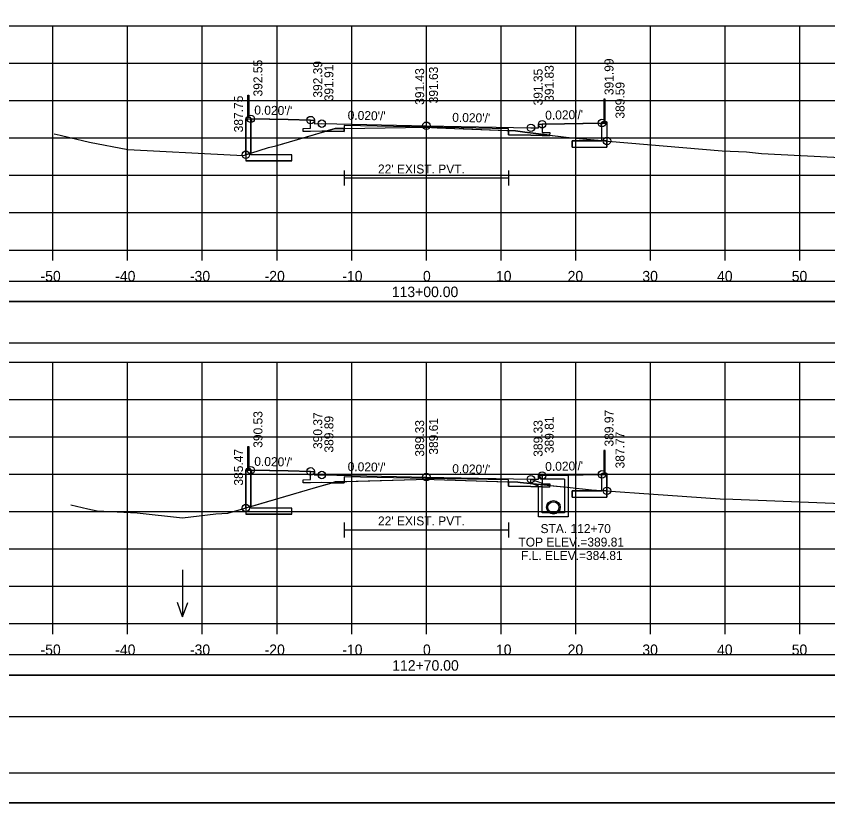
# Model space of a CAD drawing. Extents: x -37291014 to -37290680, y -936053 to -933067.
# Drawn here: x -37290898 to -37290789.4, y -933493.3 to -933388 of the extents above; entities that cross this region are included whole.
import ezdxf

# ---------------------------------------------------------------- set-up
doc = ezdxf.new("R2010")
doc.units = 0
for name, color, linetype in [('Default', 7, 'Continuous'), ('R_Alt Surface', 7, 'Continuous'), ('R_Axis', 7, 'Continuous'), ('R_Axis Annot', 7, 'Continuous'), ('R_Border', 7, 'Continuous'), ('R_Contours', 7, 'Continuous'), ('R_Exist Surface', 7, 'Continuous'), ('R_Fin Surface', 7, 'Continuous'), ('R_Grid', 7, 'Continuous'), ('R_No Plot', 7, 'Continuous'), ('R_Water', 7, 'Continuous'), ('R_Water Annot', 7, 'Continuous'), ('R_Xsect Elev', 7, 'Continuous'), ('R_Xsect Slope', 7, 'Continuous')]:
    doc.layers.add(name, color=color, linetype=linetype)

msp = doc.modelspace()

# ---------------------------------------------------------------- linework, layer by layer
at = {"layer": 'Default'}
for p, q in [((-37290867.02, -933401.53), (-37290867.02, -933398.53)), ((-37290867.02, -933398.53), (-37290866.85, -933398.53)), ((-37290866.85, -933398.53), (-37290866.85, -933401.53)), ((-37290819.35, -933399.09), (-37290819.35, -933402.09)), ((-37290819.18, -933399.09), (-37290819.35, -933399.09)), ((-37290819.18, -933402.09), (-37290819.18, -933399.09)), ((-37290867.21, -933401.55), (-37290867.27, -933401.61)), ((-37290867.27, -933401.61), (-37290867.27, -933407.35)), ((-37290866.66, -933401.53), (-37290867.21, -933401.53)), ((-37290867.21, -933401.53), (-37290867.21, -933401.55)), ((-37290866.66, -933401.55), (-37290867.21, -933401.55)), ((-37290866.66, -933401.55), (-37290866.66, -933401.53)), ((-37290866.6, -933401.61), (-37290866.66, -933401.55)), ((-37290866.6, -933406.52), (-37290866.6, -933401.61)), ((-37290819.6, -933402.17), (-37290819.54, -933402.11)), ((-37290819.6, -933404.68), (-37290819.6, -933402.17)), ((-37290819.54, -933402.09), (-37290819, -933402.09)), ((-37290819.54, -933402.11), (-37290819.54, -933402.09)), ((-37290819.54, -933402.11), (-37290819, -933402.11)), ((-37290819, -933402.09), (-37290819, -933402.11)), ((-37290819, -933402.11), (-37290818.93, -933402.17)), ((-37290818.93, -933402.17), (-37290818.93, -933405.51)), ((-37290823.6, -933405.51), (-37290823.6, -933404.68)), ((-37290823.6, -933404.68), (-37290819.6, -933404.68)), ((-37290823.6, -933405.51), (-37290818.93, -933405.51)), ((-37290861.1, -933406.52), (-37290866.6, -933406.52)), ((-37290861.1, -933407.35), (-37290861.1, -933406.52)), ((-37290861.1, -933407.35), (-37290867.27, -933407.35)), ((-37290867.02, -933448.56), (-37290867.02, -933445.56)), ((-37290867.02, -933445.56), (-37290866.85, -933445.56)), ((-37290866.85, -933445.56), (-37290866.85, -933448.56)), ((-37290819.35, -933446.12), (-37290819.35, -933449.12)), ((-37290819.18, -933446.12), (-37290819.35, -933446.12)), ((-37290819.18, -933449.12), (-37290819.18, -933446.12)), ((-37290867.21, -933448.58), (-37290867.27, -933448.64)), ((-37290867.27, -933448.64), (-37290867.27, -933454.63)), ((-37290866.66, -933448.56), (-37290867.21, -933448.56)), ((-37290867.21, -933448.56), (-37290867.21, -933448.58)), ((-37290866.66, -933448.58), (-37290867.21, -933448.58)), ((-37290866.66, -933448.58), (-37290866.66, -933448.56)), ((-37290866.6, -933448.64), (-37290866.66, -933448.58)), ((-37290866.6, -933453.8), (-37290866.6, -933448.64)), ((-37290819.6, -933449.2), (-37290819.54, -933449.14)), ((-37290819.6, -933451.5), (-37290819.6, -933449.2)), ((-37290819.54, -933449.12), (-37290819, -933449.12)), ((-37290819.54, -933449.14), (-37290819.54, -933449.12)), ((-37290819.54, -933449.14), (-37290819, -933449.14)), ((-37290819, -933449.12), (-37290819, -933449.14)), ((-37290819, -933449.14), (-37290818.93, -933449.2)), ((-37290818.93, -933449.2), (-37290818.93, -933452.33)), ((-37290823.6, -933452.33), (-37290823.6, -933451.5)), ((-37290823.6, -933451.5), (-37290819.6, -933451.5)), ((-37290823.6, -933452.33), (-37290818.93, -933452.33)), ((-37290861.1, -933454.63), (-37290867.27, -933454.63)), ((-37290861.1, -933453.8), (-37290866.6, -933453.8)), ((-37290861.1, -933454.63), (-37290861.1, -933453.8))]:
    msp.add_line(p, q, dxfattribs=at)
for points in [[(-37290866.52, -933402.22), (-37290866.6, -933402.22), (-37290866.6, -933401.72), (-37290866.52, -933401.72), (-37290866.52, -933402.22)], [(-37290819.68, -933402.78), (-37290819.6, -933402.78), (-37290819.6, -933402.28), (-37290819.68, -933402.28), (-37290819.68, -933402.78)], [(-37290866.52, -933449.24), (-37290866.6, -933449.24), (-37290866.6, -933448.74), (-37290866.52, -933448.74), (-37290866.52, -933449.24)], [(-37290819.68, -933449.8), (-37290819.6, -933449.8), (-37290819.6, -933449.3), (-37290819.68, -933449.3), (-37290819.68, -933449.8)]]:
    msp.add_lwpolyline(points, dxfattribs=at)
for points in [[(-37290992.31, -933426.17), (-37290693.89, -933426.17), (-37290693.89, -933423.47), (-37290992.31, -933423.47)], [(-37290992.31, -933431.7), (-37290693.89, -933431.7), (-37290693.89, -933426.17), (-37290992.31, -933426.17)], [(-37290992.31, -933476.17), (-37290693.89, -933476.17), (-37290693.89, -933473.47), (-37290992.31, -933473.47)], [(-37290992.31, -933481.7), (-37290693.89, -933481.7), (-37290693.89, -933476.17), (-37290992.31, -933476.17)]]:
    msp.add_lwpolyline(points, close=True, dxfattribs=at)
at = {"layer": 'R_Alt Surface'}
for points in [[(-37290827.6, -933402.44), (-37290827.6, -933403.53), (-37290826.59, -933403.55), (-37290826.6, -933403.97), (-37290827.6, -933403.95), (-37290829.1, -933403.92), (-37290832.1, -933403.86), (-37290832.1, -933403.03), (-37290843.1, -933402.81), (-37290854.1, -933402.59), (-37290854.1, -933403.42), (-37290857.1, -933403.36), (-37290858.6, -933403.39), (-37290859.6, -933403.41), (-37290859.61, -933402.99), (-37290858.6, -933402.97), (-37290858.6, -933401.88)], [(-37290854.1, -933408.63), (-37290854.1, -933410.63)], [(-37290832.1, -933408.63), (-37290832.1, -933410.63)], [(-37290854.1, -933409.63), (-37290832.1, -933409.63)], [(-37290827.6, -933449.46), (-37290827.6, -933450.56), (-37290826.59, -933450.58), (-37290826.6, -933450.99), (-37290827.6, -933450.97), (-37290829.1, -933450.94), (-37290832.1, -933450.88), (-37290832.1, -933450.05), (-37290843.1, -933449.83), (-37290854.1, -933449.61), (-37290854.1, -933450.44), (-37290857.1, -933450.38), (-37290858.6, -933450.41), (-37290859.6, -933450.43), (-37290859.61, -933450.02), (-37290858.6, -933450), (-37290858.6, -933448.9)], [(-37290854.1, -933455.73), (-37290854.1, -933457.73)], [(-37290832.1, -933455.73), (-37290832.1, -933457.73)], [(-37290854.1, -933456.73), (-37290832.1, -933456.73)]]:
    msp.add_lwpolyline(points, dxfattribs=at)
at = {"layer": 'R_Axis'}
for p, q in [((-37290993.1, -933419.27), (-37290693.1, -933419.27)), ((-37290893.1, -933420.67), (-37290893.1, -933419.27)), ((-37290883.1, -933420.67), (-37290883.1, -933419.27)), ((-37290873.1, -933420.67), (-37290873.1, -933419.27)), ((-37290863.1, -933420.67), (-37290863.1, -933419.27)), ((-37290853.1, -933420.67), (-37290853.1, -933419.27)), ((-37290843.1, -933420.67), (-37290843.1, -933419.27)), ((-37290833.1, -933420.67), (-37290833.1, -933419.27)), ((-37290823.1, -933420.67), (-37290823.1, -933419.27)), ((-37290813.1, -933420.67), (-37290813.1, -933419.27)), ((-37290803.1, -933420.67), (-37290803.1, -933419.27)), ((-37290793.1, -933420.67), (-37290793.1, -933419.27)), ((-37290993.1, -933469.27), (-37290693.1, -933469.27)), ((-37290893.1, -933470.67), (-37290893.1, -933469.27)), ((-37290883.1, -933470.67), (-37290883.1, -933469.27)), ((-37290873.1, -933470.67), (-37290873.1, -933469.27)), ((-37290863.1, -933470.67), (-37290863.1, -933469.27)), ((-37290853.1, -933470.67), (-37290853.1, -933469.27)), ((-37290843.1, -933470.67), (-37290843.1, -933469.27)), ((-37290833.1, -933470.67), (-37290833.1, -933469.27)), ((-37290823.1, -933470.67), (-37290823.1, -933469.27)), ((-37290813.1, -933470.67), (-37290813.1, -933469.27)), ((-37290803.1, -933470.67), (-37290803.1, -933469.27)), ((-37290793.1, -933470.67), (-37290793.1, -933469.27))]:
    msp.add_line(p, q, dxfattribs=at)
at = {"layer": 'R_Border'}
msp.add_line((-37290684.92, -933489.27), (-37291001.1, -933489.27), dxfattribs=at)
at = {"layer": 'R_Contours'}
for p, q in [((-37290866.6, -933402.22), (-37290866.6, -933406.3)), ((-37290856.56, -933403.37), (-37290854.1, -933403.42)), ((-37290854.1, -933403.42), (-37290854.1, -933402.99)), ((-37290832.1, -933403.29), (-37290832.1, -933403.03)), ((-37290832.1, -933403.29), (-37290832.1, -933403.86)), ((-37290819.6, -933404.62), (-37290819.6, -933402.78)), ((-37290819.6, -933404.68), (-37290823.6, -933404.68)), ((-37290823.6, -933404.68), (-37290823.6, -933405.51)), ((-37290818.93, -933404.68), (-37290819.6, -933404.62)), ((-37290819.6, -933404.62), (-37290819.6, -933404.68)), ((-37290823.6, -933405.51), (-37290818.93, -933405.51)), ((-37290866.6, -933406.3), (-37290867.27, -933406.52)), ((-37290866.6, -933406.52), (-37290866.6, -933406.3)), ((-37290861.1, -933406.52), (-37290866.6, -933406.52)), ((-37290861.1, -933407.35), (-37290861.1, -933406.52)), ((-37290867.27, -933407.35), (-37290861.1, -933407.35)), ((-37290866.6, -933449.24), (-37290866.6, -933453.61)), ((-37290855.71, -933450.41), (-37290854.1, -933450.44)), ((-37290854.1, -933450.44), (-37290854.1, -933450.25)), ((-37290832.1, -933450.3), (-37290832.1, -933450.05)), ((-37290832.1, -933450.3), (-37290832.1, -933450.88)), ((-37290826.6, -933450.79), (-37290824.25, -933451.03)), ((-37290819.6, -933451.5), (-37290823.6, -933451.5)), ((-37290823.6, -933451.5), (-37290823.6, -933452.33)), ((-37290819.6, -933451.45), (-37290819.6, -933451.5)), ((-37290818.93, -933451.5), (-37290819.6, -933451.45)), ((-37290823.6, -933452.33), (-37290818.93, -933452.33)), ((-37290866.6, -933453.61), (-37290867.27, -933453.8)), ((-37290866.6, -933453.8), (-37290866.6, -933453.61)), ((-37290867.27, -933454.63), (-37290861.1, -933454.63)), ((-37290861.1, -933453.8), (-37290866.6, -933453.8)), ((-37290861.1, -933454.63), (-37290861.1, -933453.8))]:
    msp.add_line(p, q, dxfattribs=at)
for points in [[(-37290866.52, -933401.72), (-37290866.52, -933402.22), (-37290866.6, -933402.22)], [(-37290858.6, -933401.88), (-37290861.6, -933401.82), (-37290866.52, -933401.72)], [(-37290856.56, -933403.37), (-37290857.1, -933403.36), (-37290858.6, -933403.39), (-37290859.6, -933403.41), (-37290859.61, -933402.99), (-37290858.6, -933402.97), (-37290858.6, -933401.88)], [(-37290832.1, -933403.03), (-37290843.1, -933402.81), (-37290854.1, -933402.59), (-37290854.1, -933402.99)], [(-37290819.68, -933402.28), (-37290824.6, -933402.38), (-37290827.6, -933402.44)], [(-37290827.6, -933402.44), (-37290827.6, -933403.53), (-37290826.59, -933403.55), (-37290826.6, -933403.9)], [(-37290819.6, -933402.78), (-37290819.68, -933402.78), (-37290819.68, -933402.28)], [(-37290866.6, -933406.3), (-37290864.22, -933405.53), (-37290863.27, -933405.31), (-37290856.56, -933403.37)], [(-37290854.1, -933402.99), (-37290855.3, -933403), (-37290856.56, -933403.37)], [(-37290854.1, -933402.99), (-37290854.05, -933402.99), (-37290843.19, -933402.84), (-37290841.66, -933402.9), (-37290832.1, -933403.29)], [(-37290826.6, -933403.9), (-37290829.94, -933403.48), (-37290831.18, -933403.33), (-37290832.1, -933403.29)], [(-37290832.1, -933403.86), (-37290829.1, -933403.92), (-37290827.6, -933403.95), (-37290826.6, -933403.97), (-37290826.6, -933403.9)], [(-37290826.6, -933403.9), (-37290823.64, -933404.27), (-37290819.6, -933404.62)], [(-37290818.93, -933405.51), (-37290818.93, -933404.68), (-37290818.93, -933404.68)], [(-37290867.27, -933406.52), (-37290867.27, -933406.52), (-37290867.27, -933407.35)], [(-37290866.52, -933448.74), (-37290866.52, -933449.24), (-37290866.6, -933449.24)], [(-37290858.6, -933448.9), (-37290861.6, -933448.84), (-37290866.52, -933448.74)], [(-37290855.71, -933450.41), (-37290857.1, -933450.38), (-37290858.6, -933450.41), (-37290859.6, -933450.43), (-37290859.61, -933450.02), (-37290858.6, -933450), (-37290858.6, -933448.9)], [(-37290818.93, -933451.5), (-37290818.93, -933449.3), (-37290819.6, -933449.3), (-37290824.6, -933449.4), (-37290827.6, -933449.46)], [(-37290866.6, -933453.61), (-37290858.25, -933451.16), (-37290855.71, -933450.41)], [(-37290854.1, -933450.25), (-37290855.3, -933450.29), (-37290855.71, -933450.41)], [(-37290832.1, -933450.05), (-37290843.1, -933449.83), (-37290854.1, -933449.61), (-37290854.1, -933450.25)], [(-37290854.1, -933450.25), (-37290844.46, -933449.97), (-37290843.27, -933449.93), (-37290842.07, -933449.97), (-37290832.1, -933450.3)], [(-37290826.6, -933450.79), (-37290830.56, -933450.39), (-37290830.84, -933450.34), (-37290832.1, -933450.3)], [(-37290827.6, -933449.46), (-37290827.6, -933450.56), (-37290826.59, -933450.58), (-37290826.6, -933450.79)], [(-37290832.1, -933450.88), (-37290829.1, -933450.94), (-37290827.6, -933450.97), (-37290826.6, -933450.99), (-37290826.6, -933450.79)], [(-37290824.25, -933451.03), (-37290820.98, -933451.35), (-37290818.93, -933451.5)], [(-37290818.93, -933452.33), (-37290818.93, -933451.5), (-37290818.93, -933451.5)], [(-37290867.27, -933453.8), (-37290867.27, -933453.8), (-37290867.27, -933454.63)]]:
    msp.add_lwpolyline(points, dxfattribs=at)
at = {"layer": 'R_Exist Surface'}
for points in [[(-37290892.92, -933403.72), (-37290892.15, -933403.91), (-37290890.85, -933404.21), (-37290888.19, -933404.84), (-37290883.08, -933405.8), (-37290869.37, -933406.53), (-37290867.6, -933406.62), (-37290864.22, -933405.53), (-37290863.27, -933405.31), (-37290855.3, -933403), (-37290854.05, -933402.99), (-37290843.19, -933402.84), (-37290841.66, -933402.9), (-37290831.18, -933403.33), (-37290829.94, -933403.48), (-37290823.64, -933404.27), (-37290818.76, -933404.69), (-37290803.51, -933406), (-37290800.23, -933406.12), (-37290798.22, -933406.34), (-37290786.8, -933406.94)], [(-37290890.71, -933453.36), (-37290888.42, -933453.9), (-37290887.18, -933454.2), (-37290881.8, -933454.45), (-37290875.74, -933455.12), (-37290871.29, -933454.6), (-37290869.68, -933454.51), (-37290858.25, -933451.16), (-37290855.3, -933450.29), (-37290844.46, -933449.97), (-37290843.27, -933449.93), (-37290842.07, -933449.97), (-37290830.84, -933450.34), (-37290830.56, -933450.39), (-37290824.25, -933451.03), (-37290820.98, -933451.35), (-37290810.78, -933452.07), (-37290803.79, -933452.58), (-37290802.09, -933452.63), (-37290784.1, -933453.35)]]:
    msp.add_lwpolyline(points, dxfattribs=at)
at = {"layer": 'R_Fin Surface'}
for points in [[(-37290867.27, -933406.52), (-37290867.27, -933401.72), (-37290866.6, -933401.72), (-37290861.6, -933401.82), (-37290858.6, -933401.88), (-37290858.1, -933401.88), (-37290858.1, -933402.38), (-37290857.1, -933402.36), (-37290843.1, -933402.64), (-37290829.1, -933402.92), (-37290828.1, -933402.94), (-37290828.1, -933402.44), (-37290827.6, -933402.44), (-37290824.6, -933402.38), (-37290819.6, -933402.28), (-37290818.93, -933402.28), (-37290818.93, -933404.68)], [(-37290867.27, -933453.8), (-37290867.27, -933448.74), (-37290866.6, -933448.74), (-37290861.6, -933448.84), (-37290858.6, -933448.9), (-37290858.1, -933448.9), (-37290858.1, -933449.4), (-37290857.1, -933449.38), (-37290843.1, -933449.66), (-37290829.1, -933449.94), (-37290828.1, -933449.96), (-37290828.1, -933449.46), (-37290827.6, -933449.46), (-37290824.6, -933449.4), (-37290819.6, -933449.3), (-37290818.93, -933449.3), (-37290818.93, -933451.5)]]:
    msp.add_lwpolyline(points, dxfattribs=at)
at = {"layer": 'R_Grid'}
for p, q in [((-37290993.1, -933389.27), (-37290693.1, -933389.27)), ((-37290893.1, -933419.27), (-37290893.1, -933389.27)), ((-37290883.1, -933419.27), (-37290883.1, -933389.27)), ((-37290873.1, -933419.27), (-37290873.1, -933389.27)), ((-37290863.1, -933419.27), (-37290863.1, -933389.27)), ((-37290853.1, -933419.27), (-37290853.1, -933389.27)), ((-37290843.1, -933419.27), (-37290843.1, -933389.27)), ((-37290833.1, -933419.27), (-37290833.1, -933389.27)), ((-37290823.1, -933419.27), (-37290823.1, -933389.27)), ((-37290813.1, -933419.27), (-37290813.1, -933389.27)), ((-37290803.1, -933419.27), (-37290803.1, -933389.27)), ((-37290793.1, -933419.27), (-37290793.1, -933389.27)), ((-37290993.1, -933394.27), (-37290693.1, -933394.27)), ((-37290993.1, -933399.27), (-37290693.1, -933399.27)), ((-37290993.1, -933404.27), (-37290693.1, -933404.27)), ((-37290993.1, -933409.27), (-37290693.1, -933409.27)), ((-37290993.1, -933414.27), (-37290693.1, -933414.27)), ((-37290993.1, -933419.27), (-37290693.1, -933419.27)), ((-37290993.1, -933434.27), (-37290693.1, -933434.27)), ((-37290893.1, -933469.27), (-37290893.1, -933434.27)), ((-37290883.1, -933469.27), (-37290883.1, -933434.27)), ((-37290873.1, -933469.27), (-37290873.1, -933434.27)), ((-37290863.1, -933469.27), (-37290863.1, -933434.27)), ((-37290853.1, -933469.27), (-37290853.1, -933434.27)), ((-37290843.1, -933469.27), (-37290843.1, -933434.27)), ((-37290833.1, -933469.27), (-37290833.1, -933434.27)), ((-37290823.1, -933469.27), (-37290823.1, -933434.27)), ((-37290813.1, -933469.27), (-37290813.1, -933434.27)), ((-37290803.1, -933469.27), (-37290803.1, -933434.27)), ((-37290793.1, -933469.27), (-37290793.1, -933434.27)), ((-37290993.1, -933439.27), (-37290693.1, -933439.27)), ((-37290993.1, -933444.27), (-37290693.1, -933444.27)), ((-37290993.1, -933449.27), (-37290693.1, -933449.27)), ((-37290993.1, -933454.27), (-37290693.1, -933454.27)), ((-37290993.1, -933459.27), (-37290693.1, -933459.27)), ((-37290993.1, -933464.27), (-37290693.1, -933464.27)), ((-37290993.1, -933469.27), (-37290693.1, -933469.27))]:
    msp.add_line(p, q, dxfattribs=at)
at = {"layer": 'R_No Plot'}
msp.add_line((-37291013.5, -933493.25), (-37290680.17, -933493.25), dxfattribs=at)
for points in [[(-37291013.51, -933279.91), (-37290680.17, -933279.91), (-37290680.17, -933493.25), (-37291013.51, -933493.25)], [(-37290767.18, -933283.81), (-37290747.56, -933283.81), (-37290747.56, -933293.69), (-37290731.45, -933293.69), (-37290708.25, -933293.69), (-37290708.25, -933318.02), (-37290684.92, -933318.02), (-37290684.92, -933489.27), (-37291001.1, -933489.27), (-37291001.1, -933283.81)]]:
    msp.add_lwpolyline(points, close=True, dxfattribs=at)
for centre, radius in [((-37290866.6, -933401.72), 0.5), ((-37290858.6, -933401.88), 0.5), ((-37290857.1, -933402.36), 0.5), ((-37290843.1, -933402.64), 0.5), ((-37290829.1, -933402.92), 0.5), ((-37290829.1, -933402.92), 0.5), ((-37290827.6, -933402.44), 0.5), ((-37290819.6, -933402.28), 0.5), ((-37290818.93, -933404.68), 0.5), ((-37290867.27, -933406.52), 0.5), ((-37290866.6, -933448.74), 0.5), ((-37290858.6, -933448.9), 0.5), ((-37290857.1, -933449.38), 0.5), ((-37290843.1, -933449.66), 0.5), ((-37290827.6, -933449.46), 0.5), ((-37290819.6, -933449.3), 0.5), ((-37290829.1, -933449.94), 0.5), ((-37290829.1, -933449.94), 0.5), ((-37290818.93, -933451.5), 0.5), ((-37290867.27, -933453.8), 0.5), ((-37290826.1, -933453.71), 0.917)]:
    msp.add_circle(centre, radius, dxfattribs=at)
at = {"layer": 'R_Water'}
for p, q in [((-37290829.1, -933449.94), (-37290827.6, -933450.46)), ((-37290829.1, -933450.47), (-37290828.1, -933450.82)), ((-37290827.93, -933449.63), (-37290827.85, -933449.46)), ((-37290827.93, -933449.63), (-37290827.6, -933449.96)), ((-37290824.1, -933449.46), (-37290827.85, -933449.46)), ((-37290824.6, -933449.96), (-37290827.6, -933449.96)), ((-37290827.6, -933450.96), (-37290827.6, -933450.46)), ((-37290828.1, -933450.96), (-37290828.1, -933450.82))]:
    msp.add_line(p, q, dxfattribs=at)
for points in [[(-37290829.1, -933450.47), (-37290829.1, -933449.94)], [(-37290824.1, -933449.46), (-37290824.1, -933454.96), (-37290826.1, -933454.96), (-37290828.1, -933454.96), (-37290828.1, -933450.96)], [(-37290824.6, -933449.96), (-37290824.6, -933454.46), (-37290826.1, -933454.46), (-37290827.6, -933454.46), (-37290827.6, -933450.96)]]:
    msp.add_lwpolyline(points, dxfattribs=at)
msp.add_circle((-37290826.1, -933453.71), 0.75, dxfattribs=at)
at = {"layer": 'R_Water Annot'}
for p, q in [((-37290875.74, -933462.08), (-37290875.74, -933468.37)), ((-37290875.74, -933468.37), (-37290876.44, -933466.45)), ((-37290875.74, -933468.37), (-37290875.04, -933466.45))]:
    msp.add_line(p, q, dxfattribs=at)
at = {"layer": 'R_Xsect Elev'}
for p, q in [((-37290843.1, -933402.84), (-37290843.1, -933392.84)), ((-37290843.1, -933449.93), (-37290843.1, -933439.93))]:
    msp.add_line(p, q, dxfattribs=at)

# ---------------------------------------------------------------- texts
at = {"layer": 'R_Axis Annot'}
for s, p in [('-50', (-37290894.76, -933423.47)), ('-40', (-37290884.76, -933423.47)), ('-30', (-37290874.76, -933423.47)), ('-20', (-37290864.76, -933423.47)), ('-10', (-37290854.36, -933423.47)), ('0', (-37290843.56, -933423.47)), ('10', (-37290833.79, -933423.47)), ('20', (-37290824.19, -933423.47)), ('30', (-37290814.19, -933423.47)), ('40', (-37290804.19, -933423.47)), ('50', (-37290794.19, -933423.47)), ('113+00.00', (-37290847.73, -933425.57)), ('-50', (-37290894.76, -933473.47)), ('-40', (-37290884.76, -933473.47)), ('-30', (-37290874.76, -933473.47)), ('-20', (-37290864.76, -933473.47)), ('-10', (-37290854.36, -933473.47)), ('0', (-37290843.56, -933473.47)), ('10', (-37290833.79, -933473.47)), ('20', (-37290824.19, -933473.47)), ('30', (-37290814.19, -933473.47)), ('40', (-37290804.19, -933473.47)), ('50', (-37290794.19, -933473.47)), ('112+70.00', (-37290847.67, -933475.57))]:
    msp.add_text(s, height=1.4, dxfattribs=at).set_placement(p)
at = {"layer": 'R_Water'}
for p in [(-37290849.58, -933409.03), (-37290849.58, -933456.13)]:
    msp.add_text("22' EXIST. PVT.", height=1.2, dxfattribs=at).set_placement(p)
at = {"layer": 'R_Water Annot'}
for s, p in [('STA. 112+70', (-37290827.82, -933457.16)), ('TOP ELEV.=389.81', (-37290830.78, -933458.96)), ('F.L. ELEV.=384.81', (-37290830.43, -933460.76))]:
    msp.add_text(s, height=1.2, dxfattribs=at).set_placement(p)
at = {"layer": 'R_Xsect Elev'}
for s, p in [('392.55', (-37290865.05, -933398.72)), ('391.99', (-37290818.05, -933398.54)), ('392.39', (-37290857.05, -933398.88)), ('391.91', (-37290855.55, -933399.36)), ('391.43', (-37290843.4, -933399.84)), ('391.63', (-37290841.55, -933399.64)), ('391.35', (-37290827.55, -933399.92)), ('391.35', (-37290827.55, -933399.92)), ('391.83', (-37290826.05, -933399.44)), ('389.59', (-37290816.58, -933401.68)), ('387.75', (-37290867.65, -933403.52)), ('389.97', (-37290818.05, -933445.57)), ('390.53', (-37290865.05, -933445.74)), ('390.37', (-37290857.05, -933445.9)), ('389.89', (-37290855.55, -933446.38)), ('389.81', (-37290826.05, -933446.46)), ('389.33', (-37290843.4, -933446.93)), ('389.61', (-37290841.55, -933446.66)), ('389.33', (-37290827.55, -933446.94)), ('389.33', (-37290827.55, -933446.94)), ('387.77', (-37290816.58, -933448.5)), ('385.47', (-37290867.65, -933450.8))]:
    msp.add_text(s, height=1.2, rotation=90, dxfattribs=at).set_placement(p)
at = {"layer": 'R_Xsect Slope'}
for rotation, p in [(358.8542, (-37290866.15, -933401.13)), (1.1458, (-37290827.18, -933401.83)), (358.8542, (-37290853.65, -933401.83)), (358.8542, (-37290839.65, -933402.11)), (358.8542, (-37290866.15, -933448.15)), (358.8542, (-37290853.65, -933448.85)), (358.8542, (-37290839.65, -933449.13)), (1.1458, (-37290827.18, -933448.85))]:
    msp.add_text("0.020'/'", height=1.2, rotation=rotation, dxfattribs=at).set_placement(p)

doc.saveas('drawing.dxf')
